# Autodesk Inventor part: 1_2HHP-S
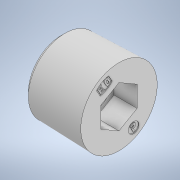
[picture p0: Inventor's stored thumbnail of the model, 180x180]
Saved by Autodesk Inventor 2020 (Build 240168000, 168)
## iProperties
Created: 2019-12
Part Number: 1_2HHP-S
Material: Generico
Description: STEP AP203
Document SubType Name: Modeling
Designer: carlo
Density: 1 g/cm^3
Appearance: Default
DataBaseUnit: MM
Sending System: PARTsolutions
Title: p:/temp/worker_143/temp/exporttempdir_2124_13_9JqMM/format_0/Adapters Hexagon socket plug 1_2HHP-S.stp
Revision Number: NONE
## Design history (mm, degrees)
feature "_Adapters Hexagon socket plug 1_2HHP-S"
node "Solido1"
